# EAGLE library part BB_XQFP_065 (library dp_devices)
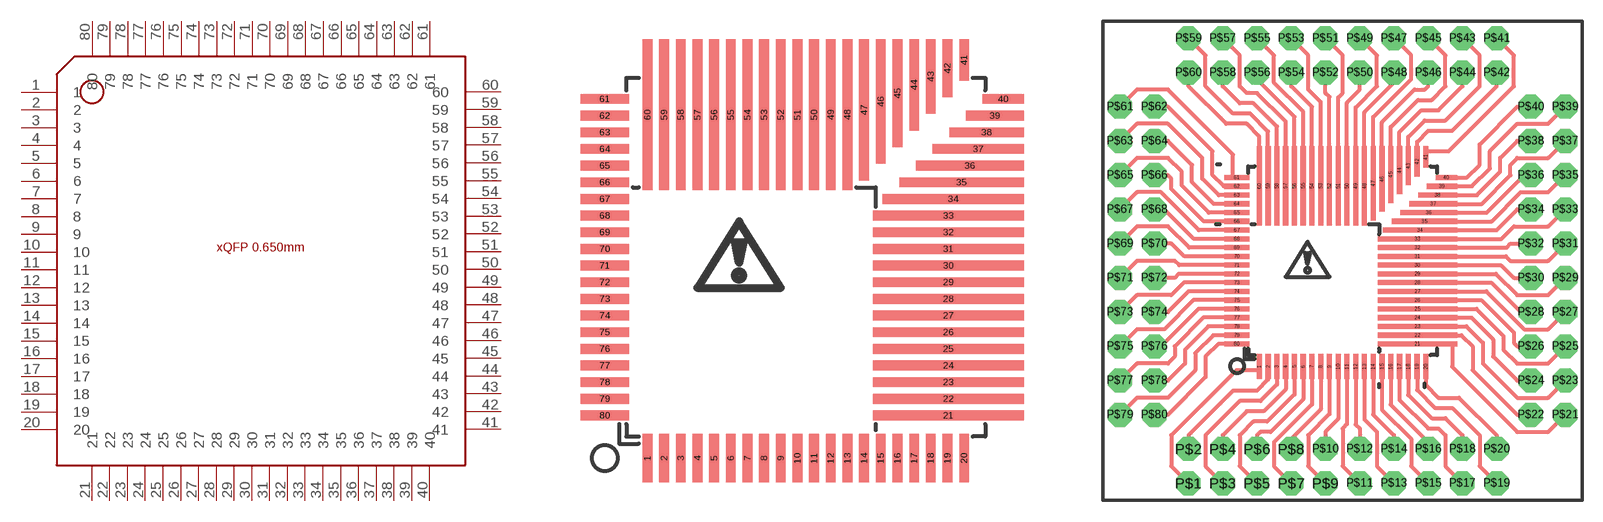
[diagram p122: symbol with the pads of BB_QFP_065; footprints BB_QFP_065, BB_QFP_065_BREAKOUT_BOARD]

Designator prefix -

## BB_XQFP_065  [BB_QFP_065]
1  1
2  2
3  3
4  4
5  5
6  6
7  7
8  8
9  9
10  10
11  11
12  12
13  13
14  14
15  15
16  16
17  17
18  18
19  19
20  20
21  21
22  22
23  23
24  24
25  25
26  26
27  27
28  28
29  29
30  30
31  31
32  32
33  33
34  34
35  35
36  36
37  37
38  38
39  39
40  40
41  41
42  42
43  43
44  44
45  45
46  46
47  47
48  48
49  49
50  50
51  51
52  52
53  53
54  54
55  55
56  56
57  57
58  58
59  59
60  60
61  61
62  62
63  63
64  64
65  65
66  66
67  67
68  68
69  69
70  70
71  71
72  72
73  73
74  74
75  75
76  76
77  77
78  78
79  79
80  80

## BB_XQFP_065BB  [BB_QFP_065_BREAKOUT_BOARD]
P$1  1
P$2  2
P$3  3
P$4  4
P$5  5
P$6  6
P$7  7
P$8  8
P$9  9
P$10  10
P$11  11
P$12  12
P$13  13
P$14  14
P$15  15
P$16  16
P$17  17
P$18  18
P$19  19
P$20  20
P$21  21
P$22  22
P$23  23
P$24  24
P$25  25
P$26  26
P$27  27
P$28  28
P$29  29
P$30  30
P$31  31
P$32  32
P$33  33
P$34  34
P$35  35
P$36  36
P$37  37
P$38  38
P$39  39
P$40  40
P$41  41
P$42  42
P$43  43
P$44  44
P$45  45
P$46  46
P$47  47
P$48  48
P$49  49
P$50  50
P$51  51
P$52  52
P$53  53
P$54  54
P$55  55
P$56  56
P$57  57
P$58  58
P$59  59
P$60  60
P$61  61
P$62  62
P$63  63
P$64  64
P$65  65
P$66  66
P$67  67
P$68  68
P$69  69
P$70  70
P$71  71
P$72  72
P$73  73
P$74  74
P$75  75
P$76  76
P$77  77
P$78  78
P$79  79
P$80  80

## Footprint BB_QFP_065 (pad centres in mm)
QFP 0.65 mm pitch 52p (10mm sq) 80p (14mm sq) CC-BY-SA
smd 0.38 x 1.875: 1 -6.175,-7.838; 2 -5.525,-7.838; 3 -4.875,-7.838; 4 -4.225,-7.838; 5 -3.575,-7.838; 6 -2.925,-7.838; 7 -2.275,-7.838; 8 -1.625,-7.838; 9 -0.975,-7.838; 10 -0.325,-7.838; 11 0.325,-7.838; 12 0.975,-7.838; 13 1.625,-7.838; 14 2.275,-7.838; 15 2.925,-7.838; 16 3.575,-7.838; 17 4.225,-7.838; 18 4.875,-7.838; 19 5.525,-7.838; 20 6.175,-7.838
smd 5.875 x 0.38: 21 5.563,-6.175; 22 5.563,-5.525; 23 5.563,-4.875; 24 5.563,-4.225; 25 5.563,-3.575; 26 5.563,-2.925; 27 5.563,-2.275; 28 5.563,-1.625; 29 5.563,-0.975; 30 5.563,-0.325; 31 5.563,0.325; 32 5.563,0.975; 33 5.563,1.625
smd 5.5 x 0.38: 34 5.75,2.275
smd 4.85 x 0.38: 35 6.075,2.925
smd 4.2 x 0.38: 36 6.4,3.575
smd 3.55 x 0.38: 37 6.725,4.225
smd 2.9 x 0.38: 38 7.05,4.875
smd 2.25 x 0.38: 39 7.375,5.525
smd 1.6 x 0.38: 40 7.7,6.175
smd 0.38 x 1.6: 41 6.175,7.7
smd 0.38 x 2.25: 42 5.525,7.375
smd 0.38 x 2.9: 43 4.875,7.05
smd 0.38 x 3.55: 44 4.225,6.725
smd 0.38 x 4.2: 45 3.575,6.4
smd 0.38 x 4.85: 46 2.925,6.075
smd 0.38 x 5.5: 47 2.275,5.75
smd 0.38 x 5.875: 48 1.625,5.563; 49 0.975,5.563; 50 0.325,5.563; 51 -0.325,5.563; 52 -0.975,5.563; 53 -1.625,5.563; 54 -2.275,5.563; 55 -2.925,5.563; 56 -3.575,5.563; 57 -4.225,5.563; 58 -4.875,5.563; 59 -5.525,5.563; 60 -6.175,5.563
smd 1.875 x 0.38: 61 -7.838,6.175; 62 -7.838,5.525; 63 -7.838,4.875; 64 -7.838,4.225; 65 -7.838,3.575; 66 -7.838,2.925; 67 -7.838,2.275; 68 -7.838,1.625; 69 -7.838,0.975; 70 -7.838,0.325; 71 -7.838,-0.325; 72 -7.838,-0.975; 73 -7.838,-1.625; 74 -7.838,-2.275; 75 -7.838,-2.925; 76 -7.838,-3.575; 77 -7.838,-4.225; 78 -7.838,-4.875; 79 -7.838,-5.525; 80 -7.838,-6.175

## Footprint BB_QFP_065_BREAKOUT_BOARD (pad centres in mm)
QFP 0.65 mm pitch 52p (10mm sq) 80p (14mm sq) CC-BY-SA
smd 0.38 x 1.875: 1 -6.175,-7.838; 2 -5.525,-7.838; 3 -4.875,-7.838; 4 -4.225,-7.838; 5 -3.575,-7.838; 6 -2.925,-7.838; 7 -2.275,-7.838; 8 -1.625,-7.838; 9 -0.975,-7.838; 10 -0.325,-7.838; 11 0.325,-7.838; 12 0.975,-7.838; 13 1.625,-7.838; 14 2.275,-7.838; 15 2.925,-7.838; 16 3.575,-7.838; 17 4.225,-7.838; 18 4.875,-7.838; 19 5.525,-7.838; 20 6.175,-7.838
smd 5.875 x 0.38: 21 5.563,-6.175; 22 5.563,-5.525; 23 5.563,-4.875; 24 5.563,-4.225; 25 5.563,-3.575; 26 5.563,-2.925; 27 5.563,-2.275; 28 5.563,-1.625; 29 5.563,-0.975; 30 5.563,-0.325; 31 5.563,0.325; 32 5.563,0.975; 33 5.563,1.625
smd 5.5 x 0.38: 34 5.75,2.275
smd 4.85 x 0.38: 35 6.075,2.925
smd 4.2 x 0.38: 36 6.4,3.575
smd 3.55 x 0.38: 37 6.725,4.225
smd 2.9 x 0.38: 38 7.05,4.875
smd 2.25 x 0.38: 39 7.375,5.525
smd 1.6 x 0.38: 40 7.7,6.175
smd 0.38 x 1.6: 41 6.175,7.7
smd 0.38 x 2.25: 42 5.525,7.375
smd 0.38 x 2.9: 43 4.875,7.05
smd 0.38 x 3.55: 44 4.225,6.725
smd 0.38 x 4.2: 45 3.575,6.4
smd 0.38 x 4.85: 46 2.925,6.075
smd 0.38 x 5.5: 47 2.275,5.75
smd 0.38 x 5.875: 48 1.625,5.563; 49 0.975,5.563; 50 0.325,5.563; 51 -0.325,5.563; 52 -0.975,5.563; 53 -1.625,5.563; 54 -2.275,5.563; 55 -2.925,5.563; 56 -3.575,5.563; 57 -4.225,5.563; 58 -4.875,5.563; 59 -5.525,5.563; 60 -6.175,5.563
smd 1.875 x 0.38: 61 -7.838,6.175; 62 -7.838,5.525; 63 -7.838,4.875; 64 -7.838,4.225; 65 -7.838,3.575; 66 -7.838,2.925; 67 -7.838,2.275; 68 -7.838,1.625; 69 -7.838,0.975; 70 -7.838,0.325; 71 -7.838,-0.325; 72 -7.838,-0.975; 73 -7.838,-1.625; 74 -7.838,-2.275; 75 -7.838,-2.925; 76 -7.838,-3.575; 77 -7.838,-4.225; 78 -7.838,-4.875; 79 -7.838,-5.525; 80 -7.838,-6.175
drill 1.016 pad 1.778 octagon: P$1 -11.43,-16.51; P$2 -11.43,-13.97; P$3 -8.89,-16.51; P$4 -8.89,-13.97; P$5 -6.35,-16.51; P$6 -6.35,-13.97; P$7 -3.81,-16.51; P$8 -3.81,-13.97; P$9 -1.27,-16.51; P$10 -1.27,-13.97; P$11 1.27,-16.51; P$12 1.27,-13.97; P$13 3.81,-16.51; P$14 3.81,-13.97; P$15 6.35,-16.51; P$16 6.35,-13.97; P$17 8.89,-16.51; P$18 8.89,-13.97; P$19 11.43,-16.51; P$20 11.43,-13.97; P$21 16.51,-11.43; P$22 13.97,-11.43; P$23 16.51,-8.89; P$24 13.97,-8.89; P$25 16.51,-6.35; P$26 13.97,-6.35; P$27 16.51,-3.81; P$28 13.97,-3.81; P$29 16.51,-1.27; P$30 13.97,-1.27; P$31 16.51,1.27; P$32 13.97,1.27; P$33 16.51,3.81; P$34 13.97,3.81; P$35 16.51,6.35; P$36 13.97,6.35; P$37 16.51,8.89; P$38 13.97,8.89; P$39 16.51,11.43; P$40 13.97,11.43; P$41 11.43,16.51; P$42 11.43,13.97; P$43 8.89,16.51; P$44 8.89,13.97; P$45 6.35,16.51; P$46 6.35,13.97; P$47 3.81,16.51; P$48 3.81,13.97; P$49 1.27,16.51; P$50 1.27,13.97; P$51 -1.27,16.51; P$52 -1.27,13.97; P$53 -3.81,16.51; P$54 -3.81,13.97; P$55 -6.35,16.51; P$56 -6.35,13.97; P$57 -8.89,16.51; P$58 -8.89,13.97; P$59 -11.43,16.51; P$60 -11.43,13.97; P$61 -16.51,11.43; P$62 -13.97,11.43; P$63 -16.51,8.89; P$64 -13.97,8.89; P$65 -16.51,6.35; P$66 -13.97,6.35; P$67 -16.51,3.81; P$68 -13.97,3.81; P$69 -16.51,1.27; P$70 -13.97,1.27; P$71 -16.51,-1.27; P$72 -13.97,-1.27; P$73 -16.51,-3.81; P$74 -13.97,-3.81; P$75 -16.51,-6.35; P$76 -13.97,-6.35; P$77 -16.51,-8.89; P$78 -13.97,-8.89; P$79 -16.51,-11.43; P$80 -13.97,-11.43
